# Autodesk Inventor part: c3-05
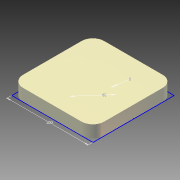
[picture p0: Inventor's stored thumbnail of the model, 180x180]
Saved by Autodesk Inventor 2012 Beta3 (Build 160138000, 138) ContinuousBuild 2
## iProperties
Created: 2010-11
Part Number: c3-05
Material: Cast Iron
Document SubType Name: Modeling
Designer: Beta-8540w
Density: 7.25 g/cm^3
Mass: 1087.5 g
Surface Area: 260 cm^2
Volume: 150 cm^3
Author: Beta-8540w
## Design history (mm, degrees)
sketch "Sketch1"
  geometry: L1 (-50, -50)-(50, -50); L2 (50, -50)-(50, 50); L3 (50, 50)-(-50, 50); L4 (-50, 50)-(-50, -50); C1 r 20 at (0, 0); C2 r 28 at (0, 0); 3 further points
  constraints: 8 end point, 3 perpendicular, 2 centre point, 2 coincident, 2 midpoint, 1 horizontal, 1 horizontal alignment, 1 parallel, 1 vertical alignment
  dimensions: "Width" = 100 distance of L1.start L1.end; "d6" = 40 diameter of C1; "d7" = 8 radial gap between concentric circles of C2 C1
extrude "Extrusion1" new body sketch "Sketch1" distance "d3" = 15; taper "d4" = 0 deg
fillet "Fillet1" dims "d5" = 14
body "Solid1"
